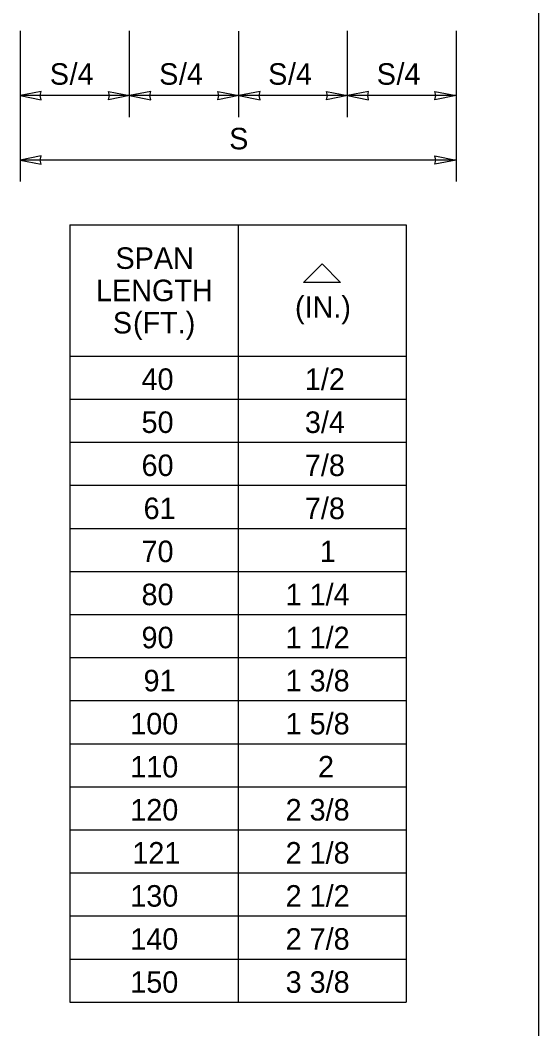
# Model space of a CAD drawing. Extents: x 99862 to 104211, y 98939 to 111076.
# Drawn here: x 102764 to 103150, y 106462 to 107212 of the extents above; entities that cross this region are included whole.
import ezdxf

# ---------------------------------------------------------------- set-up
doc = ezdxf.new("R2010")
doc.units = 0
for name, color, linetype in [('Level 15', 7, 'Continuous'), ('Level 20', 7, 'Continuous'), ('Level 40', 7, 'Continuous'), ('Level 60', 7, 'Continuous')]:
    doc.layers.add(name, color=color, linetype=linetype)

msp = doc.modelspace()

# ---------------------------------------------------------------- linework, layer by layer
at = {"layer": 'Level 15'}
for p, q in [((102764.37, 107203.91), (102764.37, 107091.91)), ((102845.69, 107139.91), (102845.69, 107203.91)), ((102927.01, 107139.91), (102927.01, 107203.8)), ((103007.74, 107139.91), (103007.74, 107203.91)), ((103088.47, 107203.91), (103088.47, 107091.91)), ((102845.69, 107155.91), (102764.37, 107155.91)), ((102927.01, 107155.91), (102845.69, 107155.91)), ((103007.74, 107155.91), (102927.01, 107155.91)), ((103088.47, 107155.91), (103007.74, 107155.91)), ((103088.47, 107107.91), (102764.37, 107107.91))]:
    msp.add_line(p, q, dxfattribs=at)
for points in [[(102764.37, 107155.91), (102780.09, 107152.82), (102779.36, 107155.91), (102780.09, 107158.99)], [(102845.69, 107155.91), (102829.97, 107152.82), (102830.69, 107155.91), (102829.97, 107158.99)], [(102845.69, 107155.91), (102861.42, 107152.82), (102860.69, 107155.91), (102861.42, 107158.99)], [(102927.01, 107155.91), (102911.29, 107152.82), (102912.02, 107155.91), (102911.29, 107158.99)], [(102927.01, 107155.91), (102942.74, 107152.82), (102942.01, 107155.91), (102942.74, 107158.99)], [(103007.74, 107155.91), (102992.02, 107152.82), (102992.75, 107155.91), (102992.02, 107158.99)], [(103007.74, 107155.91), (103023.47, 107152.82), (103022.74, 107155.91), (103023.47, 107158.99)], [(103088.47, 107155.91), (103072.75, 107152.82), (103073.48, 107155.91), (103072.75, 107158.99)], [(102764.37, 107107.91), (102780.09, 107104.82), (102779.36, 107107.91), (102780.09, 107110.99)], [(103088.47, 107107.91), (103072.75, 107104.82), (103073.48, 107107.91), (103072.75, 107110.99)]]:
    msp.add_lwpolyline(points, close=True, dxfattribs=at)
at = {"layer": 'Level 20'}
for p, q in [((102975.15, 107017.04), (102988.92, 107030.77)), ((102988.92, 107030.77), (103002.65, 107017.04)), ((103002.65, 107017.04), (102975.15, 107017.04))]:
    msp.add_line(p, q, dxfattribs=at)
at = {"layer": 'Level 40'}
for p, q in [((102801.42, 107059.91), (103051.42, 107059.91)), ((102801.42, 107059.91), (102801.42, 106482.25)), ((102926.42, 107059.91), (102926.42, 106482.25)), ((103051.42, 107059.91), (103051.42, 106482.25)), ((102801.42, 106962.25), (103051.42, 106962.25)), ((102801.42, 106930.25), (103051.42, 106930.25)), ((102801.42, 106898.25), (103051.42, 106898.25)), ((102801.42, 106866.25), (103051.42, 106866.25)), ((102801.42, 106834.25), (103051.42, 106834.25)), ((102801.42, 106802.25), (103051.42, 106802.25)), ((102801.42, 106770.25), (103051.42, 106770.25)), ((102801.42, 106738.25), (103051.42, 106738.25)), ((102801.42, 106706.25), (103051.42, 106706.25)), ((102801.42, 106674.25), (103051.42, 106674.25)), ((102801.42, 106642.25), (103051.42, 106642.25)), ((102801.42, 106610.25), (103051.42, 106610.25)), ((102801.42, 106578.25), (103051.42, 106578.25)), ((102801.42, 106546.25), (103051.42, 106546.25)), ((102801.42, 106514.25), (103051.42, 106514.25)), ((102801.42, 106482.25), (103051.42, 106482.25))]:
    msp.add_line(p, q, dxfattribs=at)
at = {"layer": 'Level 60'}
msp.add_line((103150, 106000), (103150, 108075), dxfattribs=at)

# ---------------------------------------------------------------- texts
at = {"layer": 'Level 20'}
for s, p in [('S', (102786.39, 107163.91)), ('  /4', (102789.19, 107163.91)), ('S', (102867.71, 107163.91)), ('  /4', (102870.51, 107163.91)), ('S', (102948.74, 107163.91)), ('  /4', (102951.54, 107163.91)), ('S', (103029.47, 107163.91)), ('  /4', (103032.27, 107163.91)), ('S', (102919.78, 107115.91)), ('SPAN', (102835.24, 107027.08)), ('LENGTH', (102820.75, 107003.08)), ('(IN.)', (102968.7, 106990.77)), ('S', (102833.28, 106979.08)), ('   (FT.)', (102830.44, 106979.08)), (' 40', (102848.67, 106937.15)), ('  1/2 ', (102964.17, 106937.15)), ('  3/4 ', (102964.17, 106905.15)), (' 50', (102848.67, 106905.15)), (' 60', (102848.67, 106873.15)), ('  7/8 ', (102964.17, 106873.15)), (' 61', (102850.18, 106841.15)), ('  7/8 ', (102964.17, 106841.15)), (' 70', (102848.67, 106809.15)), (' 1', (102981.23, 106809.15)), (' 80', (102848.67, 106777.15)), ('1 1/4 ', (102961.74, 106777.15)), (' 90', (102848.67, 106745.15)), ('1 1/2 ', (102961.74, 106745.15)), (' 91', (102850.18, 106713.15)), ('1 3/8 ', (102961.74, 106713.15)), ('100', (102846.25, 106681.15)), ('1 5/8 ', (102961.74, 106681.15)), ('110', (102846.25, 106649.15)), (' 2', (102979.87, 106649.15)), ('120', (102846.25, 106617.15)), ('2 3/8 ', (102961.74, 106617.15)), ('121', (102847.76, 106585.15)), ('2 1/8 ', (102961.74, 106585.15)), ('130', (102846.25, 106553.15)), ('2 1/2 ', (102961.74, 106553.15)), ('140', (102846.25, 106521.15)), ('2 7/8 ', (102961.74, 106521.15)), ('150', (102846.25, 106489.15)), ('3 3/8 ', (102961.74, 106489.15))]:
    msp.add_text(s, height=16, dxfattribs=at).set_placement(p)

doc.saveas('drawing.dxf')
